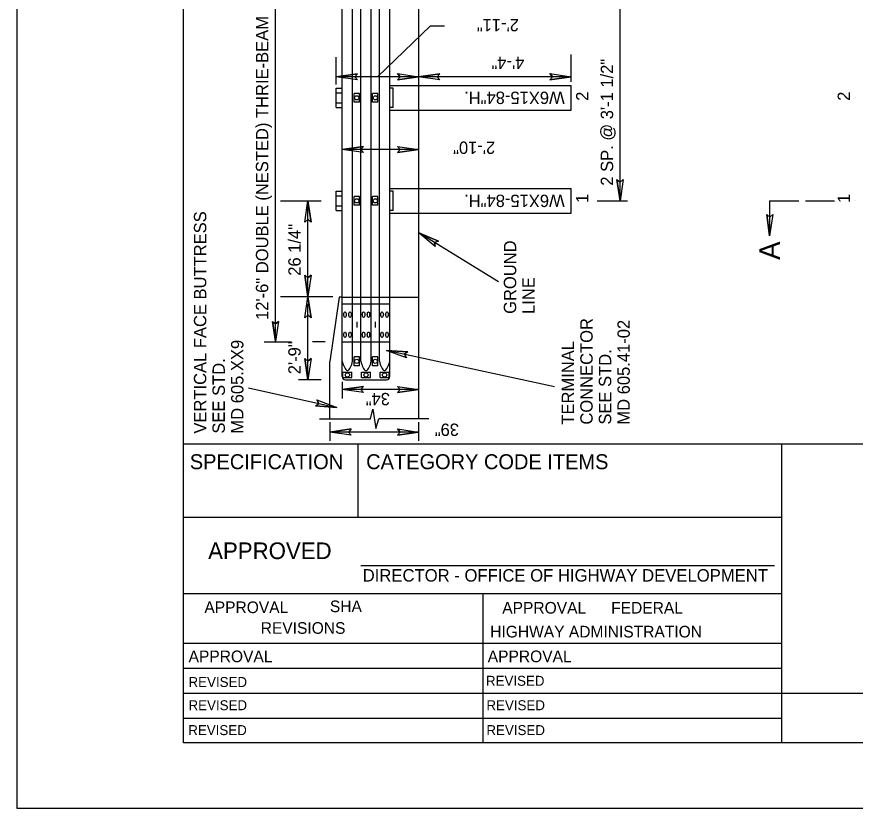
# Model space of a CAD drawing. Extents: x 12.2 to 54.5, y -7.8 to 16.1.
# Drawn here: x 46.034 to 50.1, y -7.78 to -3.938 of the extents above; entities that cross this region are included whole.
import ezdxf

# ---------------------------------------------------------------- set-up
doc = ezdxf.new("R2010")
doc.units = 0
for name, color, linetype in [('BORD-LINE', 7, 'Continuous'), ('DETL-DIMS', 7, 'Continuous'), ('DETL-LINE', 7, 'Continuous'), ('DETL-NOTE', 7, 'Continuous'), ('DETL-TITL', 7, 'Continuous'), ('TTLB-TEXT', 7, 'Continuous'), ('USER-BORD', 7, 'Continuous')]:
    doc.layers.add(name, color=color, linetype=linetype)

msp = doc.modelspace()

# ---------------------------------------------------------------- linework, layer by layer
at = {"layer": 'BORD-LINE'}
for p, q in [((49.7444, -6.0121), (46.8431, -6.0121)), ((47.6893, -6.3668), (47.6893, -6.0121)), ((49.7444, -7.4629), (49.7444, -6.0121)), ((54.2173, -6.0121), (49.7444, -6.0121)), ((46.8431, -6.3668), (49.7444, -6.3668)), ((47.7023, -6.6019), (49.7092, -6.6019)), ((46.8431, -6.7375), (47.6893, -6.7375)), ((46.8431, -7.4629), (46.8431, -6.7375)), ((46.8431, -6.7375), (49.7444, -6.7375)), ((48.2938, -6.7375), (48.2938, -7.4629)), ((46.8431, -6.9793), (49.7444, -6.9793)), ((46.8431, -7.1002), (49.7444, -7.1002)), ((46.8431, -7.2211), (49.7444, -7.2211)), ((49.7444, -7.2211), (54.2173, -7.2211)), ((46.8431, -7.342), (49.7444, -7.342)), ((47.6893, -7.342), (49.7444, -7.342))]:
    msp.add_line(p, q, dxfattribs=at)
msp.add_lwpolyline([(46.8431, 2.8902), (54.2173, 2.8902), (54.2173, -7.4629), (46.8431, -7.4629)], close=True, dxfattribs=at)
at = {"layer": 'DETL-DIMS'}
for p, q in [((47.289, -5.5129), (47.289, -1.332)), ((48.96, -4.832), (48.96, -2.832)), ((48.96, -4.832), (48.96, -3.3444)), ((48.96, -4.832), (48.96, -3.832)), ((47.7835, -4.2297), (48.0413, -3.9826)), ((48.0413, -3.9826), (48.1086, -3.9826)), ((47.5837, -4.2672), (47.5837, -4.1353)), ((48.7223, -4.2542), (48.7223, -4.1223)), ((47.687, -4.2147), (47.5837, -4.2297)), ((47.687, -4.2147), (47.674, -4.2297)), ((47.88, -4.2146), (47.9832, -4.2297)), ((47.88, -4.2146), (47.8929, -4.2297)), ((48.0865, -4.2147), (47.9832, -4.2297)), ((48.0865, -4.2147), (48.0735, -4.2297)), ((48.619, -4.2146), (48.7223, -4.2297)), ((48.619, -4.2146), (48.6319, -4.2297)), ((47.9832, -4.2297), (47.5837, -4.2297)), ((47.687, -4.2448), (47.5837, -4.2297)), ((47.687, -4.2448), (47.674, -4.2297)), ((47.8801, -4.2447), (47.9832, -4.2297)), ((47.8801, -4.2447), (47.8929, -4.2297)), ((48.7223, -4.2297), (47.9832, -4.2297)), ((48.0865, -4.2448), (47.9832, -4.2297)), ((48.0865, -4.2448), (48.0735, -4.2297)), ((48.6191, -4.2447), (48.7223, -4.2297)), ((48.6191, -4.2447), (48.6319, -4.2297)), ((50.1004, -4.332), (50.1004, -4.332)), ((50.1004, -4.332), (50.1004, -4.332)), ((47.7162, -4.5678), (47.6129, -4.5829)), ((47.9832, -4.5829), (47.6129, -4.5829)), ((47.7162, -4.5979), (47.6129, -4.5829)), ((47.7162, -4.5678), (47.7032, -4.5829)), ((47.7162, -4.5979), (47.7032, -4.5829)), ((47.88, -4.5678), (47.9832, -4.5829)), ((47.88, -4.5678), (47.8929, -4.5829)), ((47.8801, -4.5979), (47.9832, -4.5829)), ((47.8801, -4.5979), (47.8929, -4.5829)), ((48.945, -4.7286), (48.96, -4.832)), ((48.945, -4.7286), (48.96, -4.7416)), ((48.9751, -4.7286), (48.96, -4.832)), ((48.9751, -4.7286), (48.96, -4.7416)), ((47.313, -4.8316), (47.5103, -4.8316)), ((47.4313, -4.9353), (47.4463, -4.832)), ((47.4614, -4.9353), (47.4463, -4.832)), ((47.4463, -5.0819), (47.4463, -4.832)), ((48.8482, -4.832), (48.9965, -4.832)), ((49.6848, -4.8317), (49.6848, -5.001)), ((49.6848, -4.8317), (49.8264, -4.8317)), ((49.8595, -4.8323), (50.0002, -4.8323)), ((50.1004, -4.832), (50.1004, -4.832)), ((50.1004, -4.832), (50.1004, -4.832)), ((49.6713, -4.8974), (49.6848, -5.001)), ((49.6713, -4.8974), (49.6862, -4.9105)), ((49.7015, -4.8979), (49.6848, -5.001)), ((49.7015, -4.8979), (49.6862, -4.9105)), ((47.4313, -4.9353), (47.4463, -4.9224)), ((47.4614, -4.9353), (47.4463, -4.9224)), ((48.0792, -5.0279), (47.9833, -4.9864)), ((48.0634, -5.0535), (47.9833, -4.9864)), ((48.371, -5.2256), (47.9833, -4.9864)), ((48.0792, -5.0279), (47.9833, -4.9864)), ((48.0634, -5.0535), (47.9833, -4.9864)), ((48.371, -5.2256), (47.9833, -4.9864)), ((48.0792, -5.0279), (48.0602, -5.0339)), ((48.0792, -5.0279), (48.0602, -5.0339)), ((48.0634, -5.0535), (48.0602, -5.0339)), ((48.0634, -5.0535), (48.0602, -5.0339)), ((47.4463, -5.2971), (47.4463, -5.0634)), ((47.4312, -5.1926), (47.4463, -5.2959)), ((47.4312, -5.1926), (47.4463, -5.2055)), ((47.4613, -5.1926), (47.4463, -5.2959)), ((47.4613, -5.1926), (47.4463, -5.2055)), ((47.313, -5.2959), (47.5675, -5.2959)), ((47.4313, -5.4004), (47.4463, -5.2971)), ((47.4614, -5.4004), (47.4463, -5.2971)), ((47.4463, -5.5819), (47.4463, -5.332)), ((47.4313, -5.4004), (47.4463, -5.3875)), ((47.4614, -5.4004), (47.4463, -5.3875)), ((47.275, -5.4169), (47.289, -5.5129)), ((47.275, -5.4169), (47.289, -5.4289)), ((47.303, -5.4169), (47.289, -5.5129)), ((47.303, -5.4169), (47.289, -5.4289)), ((47.2337, -5.5162), (47.367, -5.5162)), ((47.5302, -5.5162), (47.4679, -5.5162)), ((47.4463, -5.7001), (47.4463, -5.5634)), ((47.9309, -5.5648), (47.8267, -5.5576)), ((47.9245, -5.5942), (47.8267, -5.5576)), ((48.6412, -5.7341), (47.8267, -5.5576)), ((47.9309, -5.5648), (47.8267, -5.5576)), ((47.9245, -5.5942), (47.8267, -5.5576)), ((48.6412, -5.7341), (47.8267, -5.5576)), ((47.9309, -5.5648), (47.9151, -5.5768)), ((47.9309, -5.5648), (47.9151, -5.5768)), ((47.4312, -5.5968), (47.4463, -5.7001)), ((47.4312, -5.5968), (47.4463, -5.6097)), ((47.4613, -5.5968), (47.4463, -5.7001)), ((47.4613, -5.5968), (47.4463, -5.6097)), ((47.9245, -5.5942), (47.9151, -5.5768)), ((47.9245, -5.5942), (47.9151, -5.5768)), ((47.5103, -5.7001), (47.4003, -5.7001)), ((47.7162, -5.7327), (47.6129, -5.7478)), ((47.7162, -5.7327), (47.7033, -5.7478)), ((47.8799, -5.7328), (47.9832, -5.7478)), ((47.8799, -5.7328), (47.8928, -5.7478)), ((47.1587, -5.74), (47.5866, -5.8353)), ((47.9832, -5.7478), (47.6129, -5.7478)), ((47.7162, -5.7628), (47.6129, -5.7478)), ((47.7162, -5.7628), (47.7033, -5.7478)), ((47.8799, -5.7628), (47.9832, -5.7478)), ((47.8799, -5.7628), (47.8928, -5.7478)), ((47.489, -5.7981), (47.5866, -5.8353)), ((47.489, -5.7981), (47.4983, -5.8156)), ((47.4824, -5.8275), (47.4983, -5.8156)), ((47.4824, -5.8275), (47.5866, -5.8353)), ((47.6561, -5.939), (47.5528, -5.9541)), ((47.9832, -5.9541), (47.5528, -5.9541)), ((47.6561, -5.9691), (47.5528, -5.9541)), ((47.6561, -5.939), (47.6432, -5.9541)), ((47.6561, -5.9691), (47.6432, -5.9541)), ((47.8799, -5.9391), (47.9832, -5.9541)), ((47.8799, -5.9391), (47.8928, -5.9541)), ((47.8799, -5.9691), (47.9832, -5.9541)), ((47.8799, -5.9691), (47.8928, -5.9541))]:
    msp.add_line(p, q, dxfattribs=at)
for points in [[(47.687, -4.2448), (47.5837, -4.2297), (47.687, -4.2147), (47.674, -4.2297)], [(47.88, -4.2146), (47.9832, -4.2297), (47.8801, -4.2447), (47.8929, -4.2297)], [(48.0865, -4.2448), (47.9832, -4.2297), (48.0865, -4.2147), (48.0735, -4.2297)], [(48.619, -4.2146), (48.7223, -4.2297), (48.6191, -4.2447), (48.6319, -4.2297)], [(47.7162, -4.5979), (47.6129, -4.5829), (47.7162, -4.5678), (47.7032, -4.5829)], [(47.88, -4.5678), (47.9832, -4.5829), (47.8801, -4.5979), (47.8929, -4.5829)], [(48.9751, -4.7286), (48.96, -4.832), (48.945, -4.7286), (48.96, -4.7416)], [(47.4313, -4.9353), (47.4463, -4.832), (47.4614, -4.9353), (47.4463, -4.9224)], [(49.7015, -4.8979), (49.6848, -5.001), (49.6713, -4.8974), (49.6862, -4.9105)], [(48.0634, -5.0535), (47.9833, -4.9864), (48.0792, -5.0279), (48.0602, -5.0339)], [(48.0634, -5.0535), (47.9833, -4.9864), (48.0792, -5.0279), (48.0602, -5.0339)], [(47.4613, -5.1926), (47.4463, -5.2959), (47.4312, -5.1926), (47.4463, -5.2055)], [(47.4313, -5.4004), (47.4463, -5.2971), (47.4614, -5.4004), (47.4463, -5.3875)], [(47.303, -5.4169), (47.289, -5.5129), (47.275, -5.4169), (47.289, -5.4289)], [(47.9245, -5.5942), (47.8267, -5.5576), (47.9309, -5.5648), (47.9151, -5.5768)], [(47.9245, -5.5942), (47.8267, -5.5576), (47.9309, -5.5648), (47.9151, -5.5768)], [(47.4613, -5.5968), (47.4463, -5.7001), (47.4312, -5.5968), (47.4463, -5.6097)], [(47.7162, -5.7628), (47.6129, -5.7478), (47.7162, -5.7327), (47.7033, -5.7478)], [(47.8799, -5.7328), (47.9832, -5.7478), (47.8799, -5.7628), (47.8928, -5.7478)], [(47.489, -5.7981), (47.5866, -5.8353), (47.4824, -5.8275), (47.4983, -5.8156)], [(47.6561, -5.9691), (47.5528, -5.9541), (47.6561, -5.939), (47.6432, -5.9541)], [(47.8799, -5.9391), (47.9832, -5.9541), (47.8799, -5.9691), (47.8928, -5.9541)]]:
    msp.add_lwpolyline(points, close=True, dxfattribs=at)
at = {"layer": 'DETL-LINE'}
for p, q in [((47.9832, 2.7851), (47.9832, -5.332)), ((47.6129, -5.332), (47.6129, -2.252)), ((47.6629, -5.332), (47.6629, -2.252)), ((47.7029, -5.332), (47.7029, -2.252)), ((47.7529, -5.332), (47.7529, -2.252)), ((47.7929, -5.332), (47.7929, -2.252)), ((47.8429, -5.332), (47.8429, -2.252)), ((47.5837, -4.2853), (47.6129, -4.2853)), ((47.5837, -4.3786), (47.5837, -4.2853)), ((47.5837, -4.3074), (47.6129, -4.3074)), ((47.8429, -4.2723), (47.9832, -4.2723)), ((47.8596, -4.2853), (47.8429, -4.2853)), ((47.8596, -4.3786), (47.8596, -4.2853)), ((47.9832, -4.2723), (48.7223, -4.2723)), ((48.7223, -4.3916), (48.7223, -4.2723)), ((47.6957, -4.3103), (47.6701, -4.3103)), ((47.6701, -4.3536), (47.6701, -4.3103)), ((47.6957, -4.3536), (47.6957, -4.3103)), ((47.7857, -4.3103), (47.7601, -4.3103)), ((47.7601, -4.3536), (47.7601, -4.3103)), ((47.7857, -4.3536), (47.7857, -4.3103)), ((47.5837, -4.3565), (47.6129, -4.3565)), ((47.5837, -4.3786), (47.6129, -4.3786)), ((47.6957, -4.3536), (47.6701, -4.3536)), ((47.7857, -4.3536), (47.7601, -4.3536)), ((47.8596, -4.3786), (47.8429, -4.3786)), ((47.8429, -4.3916), (47.9832, -4.3916)), ((47.9832, -4.3916), (48.7223, -4.3916)), ((47.5837, -4.7853), (47.6129, -4.7853)), ((47.5837, -4.8786), (47.5837, -4.7853)), ((47.8429, -4.7723), (47.9832, -4.7723)), ((47.8596, -4.7853), (47.8429, -4.7853)), ((47.8596, -4.8786), (47.8596, -4.7853)), ((47.9832, -4.7723), (48.7223, -4.7723)), ((48.7223, -4.8916), (48.7223, -4.7723)), ((47.5837, -4.8074), (47.6129, -4.8074)), ((47.6957, -4.8103), (47.6701, -4.8103)), ((47.6701, -4.8536), (47.6701, -4.8103)), ((47.6957, -4.8536), (47.6957, -4.8103)), ((47.7857, -4.8103), (47.7601, -4.8103)), ((47.7601, -4.8536), (47.7601, -4.8103)), ((47.7857, -4.8536), (47.7857, -4.8103)), ((47.5837, -4.8565), (47.6129, -4.8565)), ((47.5837, -4.8786), (47.6129, -4.8786)), ((47.6957, -4.8536), (47.6701, -4.8536)), ((47.7857, -4.8536), (47.7601, -4.8536)), ((47.8596, -4.8786), (47.8429, -4.8786)), ((47.8429, -4.8916), (47.9832, -4.8916)), ((47.9832, -4.8916), (48.7223, -4.8916)), ((47.597, -5.2986), (47.5528, -5.611)), ((47.6129, -5.2986), (47.597, -5.2986)), ((47.6129, -5.2987), (47.8429, -5.2987)), ((47.8429, -5.2987), (47.9832, -5.2987)), ((47.8429, -5.2987), (47.9832, -5.2987)), ((47.8429, -5.2987), (47.9832, -5.2987)), ((47.6129, -5.6851), (47.6129, -5.332)), ((47.6129, -5.332), (47.8429, -5.332)), ((47.6629, -5.6106), (47.6629, -5.332)), ((47.7029, -5.6106), (47.7029, -5.332)), ((47.7529, -5.6106), (47.7529, -5.332)), ((47.7929, -5.6106), (47.7929, -5.332)), ((47.8429, -5.6851), (47.8429, -5.332)), ((47.9832, -5.332), (47.9832, -5.89)), ((47.9832, -5.332), (47.9832, -5.89)), ((47.6829, -5.4192), (47.6829, -5.4468)), ((47.7729, -5.4192), (47.7729, -5.4468)), ((47.6129, -5.5162), (47.8429, -5.5162)), ((47.5528, -5.89), (47.5528, -5.611)), ((47.6957, -5.5889), (47.6701, -5.5889)), ((47.6701, -5.6322), (47.6701, -5.5889)), ((47.6957, -5.6322), (47.6957, -5.5889)), ((47.7857, -5.5889), (47.7601, -5.5889)), ((47.7601, -5.6322), (47.7601, -5.5889)), ((47.7857, -5.6322), (47.7857, -5.5889)), ((47.6957, -5.6322), (47.6701, -5.6322)), ((47.7857, -5.6322), (47.7601, -5.6322)), ((47.6163, -5.6895), (47.6163, -5.6639)), ((47.6163, -5.6639), (47.6596, -5.6639)), ((47.6163, -5.6895), (47.6596, -5.6895)), ((47.6596, -5.6895), (47.6596, -5.6639)), ((47.7063, -5.6895), (47.7063, -5.6639)), ((47.7063, -5.6639), (47.7496, -5.6639)), ((47.7063, -5.6895), (47.7496, -5.6895)), ((47.7496, -5.6895), (47.7496, -5.6639)), ((47.7963, -5.6895), (47.7963, -5.6639)), ((47.7963, -5.6639), (47.8396, -5.6639)), ((47.7963, -5.6895), (47.8396, -5.6895)), ((47.8396, -5.6895), (47.8396, -5.6639)), ((47.6129, -5.711), (47.6129, -5.7916)), ((47.6279, -5.7001), (47.8279, -5.7001)), ((47.7492, -5.89), (47.7606, -5.8437)), ((47.7606, -5.8437), (47.7755, -5.9363)), ((47.5028, -5.89), (47.7492, -5.89)), ((47.7755, -5.9363), (47.7899, -5.89)), ((48.0332, -5.89), (47.7899, -5.89)), ((47.5528, -5.9064), (47.5528, -5.9965)), ((47.9832, -5.9064), (47.9832, -5.9965))]:
    msp.add_line(p, q, dxfattribs=at)
for centre in [(47.6829, -4.332), (47.7729, -4.332), (47.6829, -4.832), (47.7729, -4.832), (47.6829, -5.6106), (47.7729, -5.6106), (47.6379, -5.6767), (47.7279, -5.6767), (47.8179, -5.6767)]:
    msp.add_circle(centre, 0.0102, dxfattribs=at)
for centre, radius, start, end in [((47.6279, -5.6851), 0.015, 180, 270), ((47.6386, -5.6468), 0.00835, 251.685, 265.5893), ((47.6373, -5.6468), 0.00835, 274.4107, 288.315), ((47.7286, -5.6468), 0.00835, 251.685, 265.5893), ((47.7273, -5.6468), 0.00835, 274.4107, 288.315), ((47.8186, -5.6468), 0.00835, 251.685, 265.5893), ((47.8173, -5.6468), 0.00835, 274.4107, 288.315), ((47.8279, -5.6851), 0.015, 270, 360)]:
    msp.add_arc(centre, radius, start, end, dxfattribs=at)
for centre in [(47.6259, -5.384), (47.6499, -5.384), (47.7159, -5.384), (47.7399, -5.384), (47.8059, -5.384), (47.8299, -5.384), (47.6259, -5.482), (47.6499, -5.482), (47.7159, -5.482), (47.7399, -5.482), (47.8059, -5.482), (47.8299, -5.482)]:
    msp.add_ellipse(centre, major_axis=(0, 0.0133), ratio=0.45311, dxfattribs=at)
for centre, major_axis, start_param, end_param in [((47.6267, -5.6222), (-0.0112, 0.0325), 1.103301, 2.957332), ((47.6491, -5.6222), (0.0112, 0.0325), 3.325853, 5.179885), ((47.7167, -5.6222), (-0.0112, 0.0325), 1.103301, 2.957332), ((47.7391, -5.6222), (0.0112, 0.0325), 3.325853, 5.179885), ((47.8067, -5.6222), (-0.0112, 0.0325), 1.103301, 2.957332), ((47.8291, -5.6222), (0.0112, 0.0325), 3.325853, 5.179885)]:
    msp.add_ellipse(centre, major_axis=major_axis, ratio=0.301091, start_param=start_param, end_param=end_param, dxfattribs=at)
at = {"layer": 'USER-BORD'}
msp.add_lwpolyline([(54.5342, 3.2202), (46.0342, 3.2202), (46.0342, -7.7798), (54.5342, -7.7798)], close=True, dxfattribs=at)

# ---------------------------------------------------------------- texts
at = {"layer": 'DETL-NOTE'}
for s, rotation, p in [('12\'-6" DOUBLE (NESTED) THRIE-BEAM', 90, (47.2539, -5.4099)), ('2\'-11"', 180, (48.4695, -3.949)), ('4\'-4"', 180, (48.4959, -4.1328)), ('2 SP. @ 3\'-1 1/2"', 90, (48.9263, -4.7583)), ('W6X15-84"H. ', 180, (48.6914, -4.302)), ('2', 90, (48.8068, -4.3466)), ('2', 90, (50.075, -4.3466)), ('2\'-10"', 180, (48.3545, -4.544)), ('W6X15-84"H. ', 180, (48.6914, -4.802)), ('1', 90, (48.8068, -4.8425)), ('1', 90, (50.075, -4.8424)), ('VERTICAL FACE BUTTRESS', 90, (46.9534, -5.9615)), ('26 1/4"', 90, (47.4111, -5.1955)), ('GROUND', 90, (48.4563, -5.3806)), ('GROUND', 90, (48.4563, -5.3806)), ('LINE', 90, (48.5463, -5.3806)), ('LINE', 90, (48.5463, -5.3806)), ('CONNECTOR', 90, (48.8271, -5.9179)), ('CONNECTOR', 90, (48.8271, -5.9179)), ('MD 605.41-02', 90, (49.0071, -5.9179)), ('MD 605.41-02', 90, (49.0071, -5.9179)), ('MD 605.XX9', 90, (47.1334, -5.9615)), ('2\'-9"', 90, (47.4111, -5.6735)), ('TERMINAL', 90, (48.7371, -5.9179)), ('TERMINAL', 90, (48.7371, -5.9179)), ('SEE STD. ', 90, (48.9171, -5.9179)), ('SEE STD. ', 90, (48.9171, -5.9179)), ('SEE STD. ', 90, (47.0434, -5.9615)), ('34"', 180, (47.8442, -5.7641)), ('39"', 180, (48.179, -5.913))]:
    msp.add_text(s, height=0.06, rotation=rotation, dxfattribs=at).set_placement(p)
at = {"layer": 'DETL-TITL'}
msp.add_text('A', height=0.1, rotation=90, dxfattribs=at).set_placement((49.7348, -5.1184))
at = {"layer": 'TTLB-TEXT'}
for s, height, p in [('SPECIFICATION', 0.07254, (46.8733, -6.1342)), ('CATEGORY CODE ITEMS ', 0.07254, (47.7286, -6.1342)), ('APPROVED', 0.0806, (46.9623, -6.5705)), ('DIRECTOR - OFFICE OF HIGHWAY DEVELOPMENT', 0.0604, (47.7118, -6.6797)), ('APPROVAL', 0.05642, (46.9441, -6.8327)), ('SHA', 0.05642, (47.5527, -6.828)), ('APPROVAL', 0.05642, (48.3887, -6.8352)), ('FEDERAL', 0.05642, (48.9168, -6.8351)), ('REVISIONS', 0.05642, (47.2172, -6.9332)), ('HIGHWAY ADMINISTRATION', 0.05642, (48.3302, -6.9509)), ('APPROVAL', 0.05642, (46.8675, -7.0709)), ('APPROVAL', 0.05642, (48.3182, -7.0709)), ('REVISED', 0.04836, (46.8672, -7.1914)), ('REVISED', 0.04836, (48.3095, -7.1855)), ('REVISED', 0.04836, (46.8672, -7.304)), ('REVISED', 0.04836, (48.3118, -7.304)), ('REVISED', 0.04836, (46.8659, -7.4248)), ('REVISED', 0.04836, (48.3118, -7.4248))]:
    msp.add_text(s, height=height, rotation=360, dxfattribs=at).set_placement(p)

doc.saveas('drawing.dxf')
